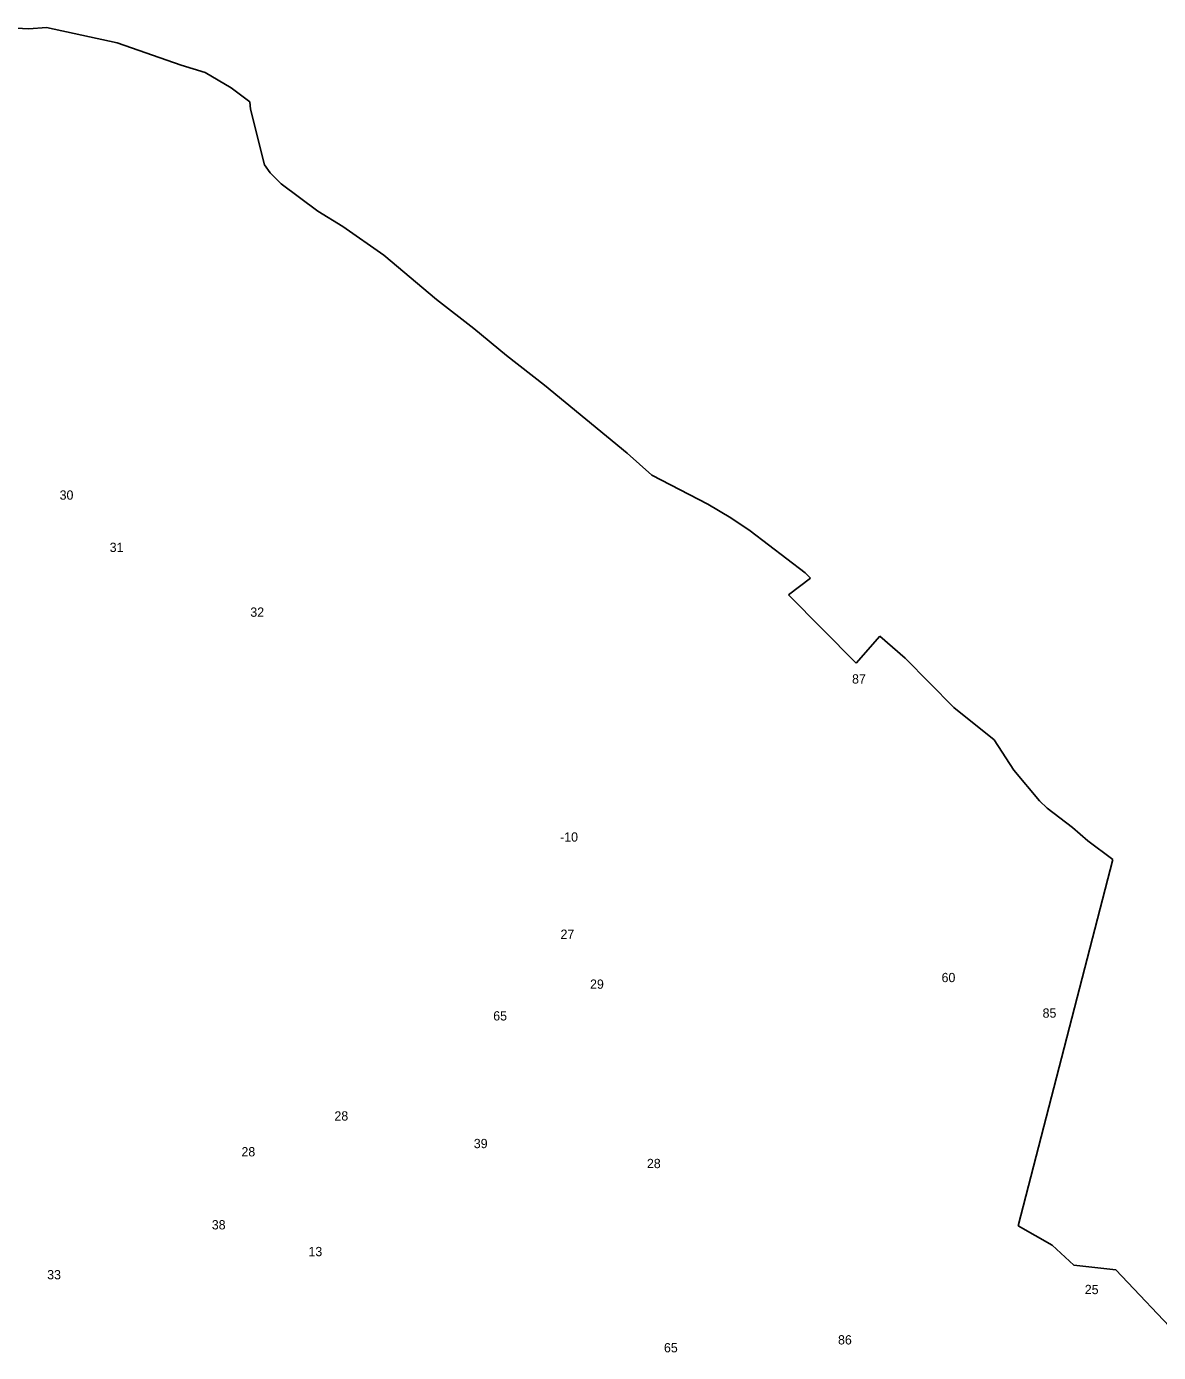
# Model space of a CAD drawing. Extents: x -772472 to -767535, y -969581 to -965387.
# Drawn here: x -770002 to -768780, y -967458 to -966027 of the extents above; entities that cross this region are included whole.
import ezdxf

# ---------------------------------------------------------------- set-up
doc = ezdxf.new("R2010")
doc.units = 0
doc.layers.add('Vrstva 13', color=7, linetype='Continuous')
doc.layers.add('Vrstva 24', color=7, linetype='Continuous')

msp = doc.modelspace()

# ---------------------------------------------------------------- linework, layer by layer
at = {"layer": 'Vrstva 13'}
for p, q in [((-770045.85, -966026.9), (-769999.51, -966029.38)), ((-769999.51, -966029.38), (-769980.3, -966028.03)), ((-769980.3, -966028.03), (-769904.13, -966044.53)), ((-769904.13, -966044.53), (-769834.96, -966068.73)), ((-769834.96, -966068.73), (-769809.18, -966076.65)), ((-769809.18, -966076.65), (-769780.93, -966093.16)), ((-769780.93, -966093.16), (-769760.81, -966108.08)), ((-769760.81, -966108.08), (-769760.13, -966116.22)), ((-769760.13, -966116.22), (-769745.21, -966176.15)), ((-769745.21, -966176.15), (-769738.89, -966184.96)), ((-769738.89, -966184.96), (-769726.91, -966196.72)), ((-769726.91, -966196.72), (-769687.58, -966226.11)), ((-769687.58, -966226.11), (-769660.68, -966242.85)), ((-769660.68, -966242.85), (-769616.15, -966273.6)), ((-769616.15, -966273.6), (-769559.42, -966321.53)), ((-769559.42, -966321.53), (-769518.96, -966352.96)), ((-769518.96, -966352.96), (-769483.93, -966381.91)), ((-769483.93, -966381.91), (-769443.01, -966414.02)), ((-769443.01, -966414.02), (-769353.72, -966487.51)), ((-769353.72, -966487.51), (-769327.05, -966511.25)), ((-769327.05, -966511.25), (-769266.69, -966542.46)), ((-769266.69, -966542.46), (-769241.82, -966557.38)), ((-769241.82, -966557.38), (-769221.03, -966571.17)), ((-769221.03, -966571.17), (-769161.58, -966616.63)), ((-769155.59, -966622.51), (-769179.32, -966640.37)), ((-769161.58, -966616.63), (-769155.59, -966622.51)), ((-769179.32, -966640.37), (-769106.54, -966714.32)), ((-769106.54, -966714.32), (-769081, -966685.15)), ((-769081, -966685.15), (-769053.65, -966708.66)), ((-769053.65, -966708.66), (-769000.98, -966762.02)), ((-769000.98, -966762.02), (-768957.58, -966797.07)), ((-768957.58, -966797.07), (-768936.17, -966829.81)), ((-768936.17, -966829.81), (-768908.76, -966862.65)), ((-768908.76, -966862.65), (-768900.39, -966870.56)), ((-768900.39, -966870.56), (-768872.81, -966891.59)), ((-768872.81, -966891.59), (-768856.31, -966906.06)), ((-768856.31, -966906.06), (-768829.41, -966926.18)), ((-768829.41, -966926.18), (-768931.58, -967321.45)), ((-768931.58, -967321.45), (-768894.96, -967342.26)), ((-768894.96, -967342.26), (-768871.68, -967363.97)), ((-768871.68, -967363.97), (-768826.02, -967369.17)), ((-768826.02, -967369.17), (-768755.5, -967443.79))]:
    msp.add_line(p, q, dxfattribs=at)

# ---------------------------------------------------------------- texts
at = {"layer": 'Vrstva 24'}
for s, p in [('30', (-769966.176, -966537.69)), ('31', (-769912.161, -966594.11)), ('32', (-769760.366, -966664.06)), ('87', (-769110.886, -966736.15)), ('-10', (-769426.005, -966906.8)), ('27', (-769425.546, -967011.75)), ('29', (-769393.69, -967065.63)), ('60', (-769014.28, -967058.5)), ('65', (-769498.18, -967099.88)), ('85', (-768905.236, -967096.86)), ('28', (-769669.556, -967207.93)), ('39', (-769519.15, -967237.69)), ('28', (-769769.936, -967246.58)), ('28', (-769332.296, -967259.27)), ('38', (-769801.936, -967325.42)), ('13', (-769697.591, -967354.31)), ('33', (-769979.606, -967379.29)), ('25', (-768859.706, -967395.26)), ('86', (-769126.03, -967449.6)), ('65', (-769313.91, -967458.12))]:
    msp.add_text(s, height=10, dxfattribs=at).set_placement(p)

doc.saveas('drawing.dxf')
